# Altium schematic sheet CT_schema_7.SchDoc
size 274 x 160 mm
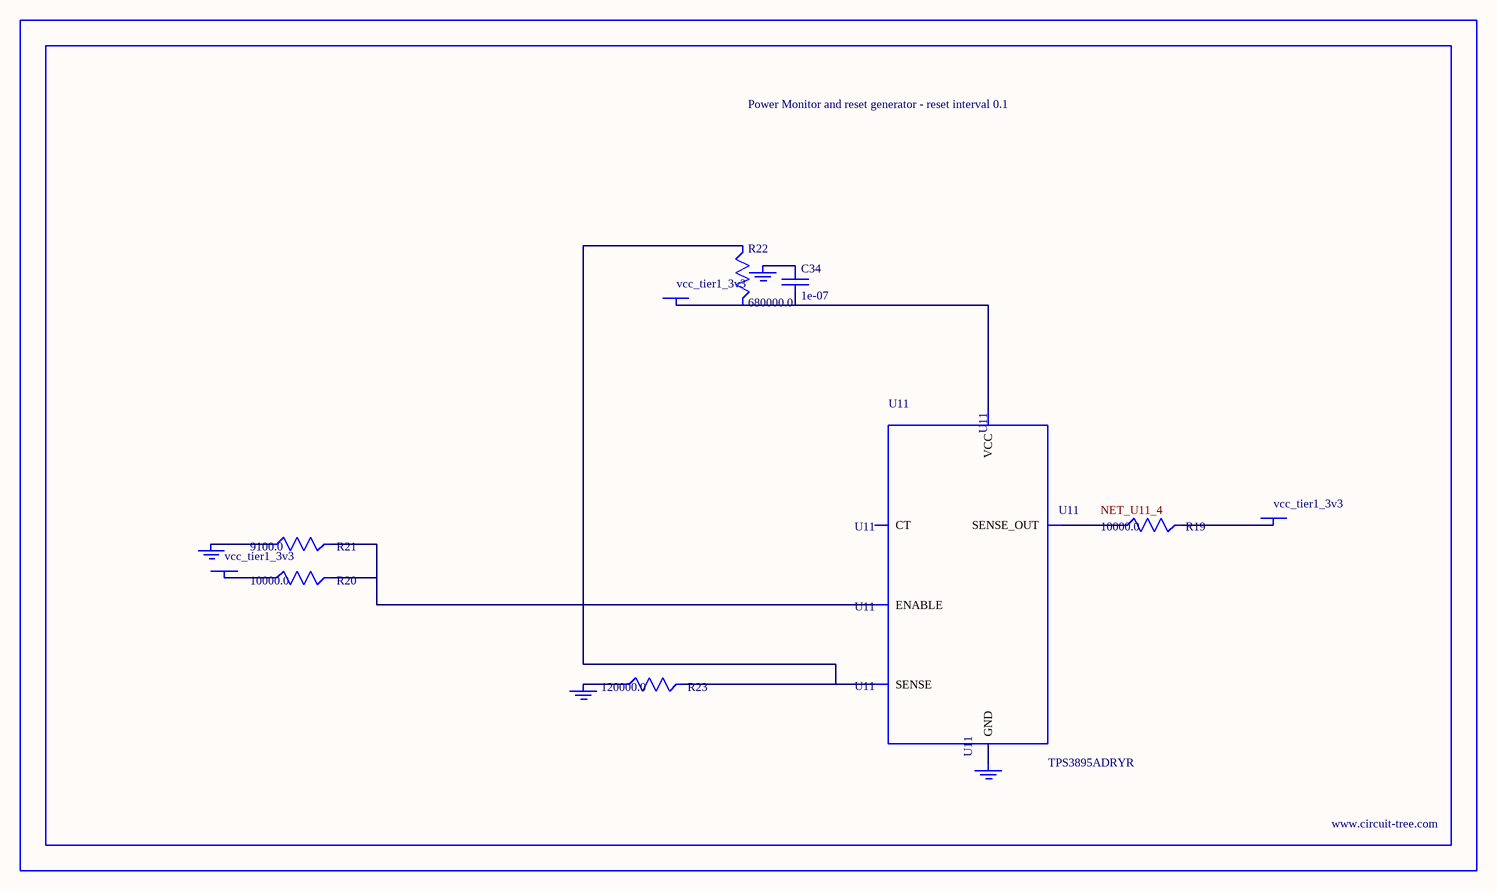
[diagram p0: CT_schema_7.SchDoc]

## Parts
BORDER6  (no value)
C34  1e-07  [C0402]
GND_INSTANCE_6_0  (no value)
GND_INSTANCE_6_1  (no value)
GND_INSTANCE_6_2  (no value)
GND_INSTANCE_6_3  (no value)
POWER_INSTANCE_6_0  vcc_tier1_3v3
POWER_INSTANCE_6_1  vcc_tier1_3v3
POWER_INSTANCE_6_2  vcc_tier1_3v3
R19  10000.0  [R0603]
R20  10000.0  [R0603]
R21  9100.0  [R0603]
R22  680000.0  [R0603]
R23  120000.0  [R0603]
U11  TPS3895ADRYR  [SON-6]

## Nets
NetC34_1: C34.1 GND_INSTANCE_6_2.0(GND)
NetC34_2: C34.2 POWER_INSTANCE_6_2.0(PWR) R22.2 U11.6(VCC)
NetGND_INSTANCE_6_0_0: GND_INSTANCE_6_0.0(GND) R21.1
NetGND_INSTANCE_6_1_0: GND_INSTANCE_6_1.0(GND) R23.1
NetGND_INSTANCE_6_3_0: GND_INSTANCE_6_3.0(GND) U11.2(GND)
NetPOWER_INSTANCE_6_0_0: POWER_INSTANCE_6_0.0(PWR) R20.1
NetPOWER_INSTANCE_6_1_0: POWER_INSTANCE_6_1.0(PWR) R19.2
NetR19_1: R19.1 U11.4(SENSE_OUT)
NetR20_2: R20.2 R21.2 U11.1(ENABLE)
NetR22_1: R22.1 R23.2 U11.3(SENSE)

Not connected (* = marked no-connect by the designer): U11 5(CT)

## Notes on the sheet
- Labels drawn without touching a wire or pin: NET_U11_4

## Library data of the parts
BORDER6 = BORDER_PAGE6
C34 = C0402C104K3RACTU
GND_INSTANCE_6_0-GND_INSTANCE_6_3 = GND
POWER_INSTANCE_6_0-POWER_INSTANCE_6_2 = PWR
R19 R20 = RC0603JR-0710KL
R21 = RC0603JR-079K1L
R22 = RC0603JR-07680KL
R23 = RC0603JR-07120KL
